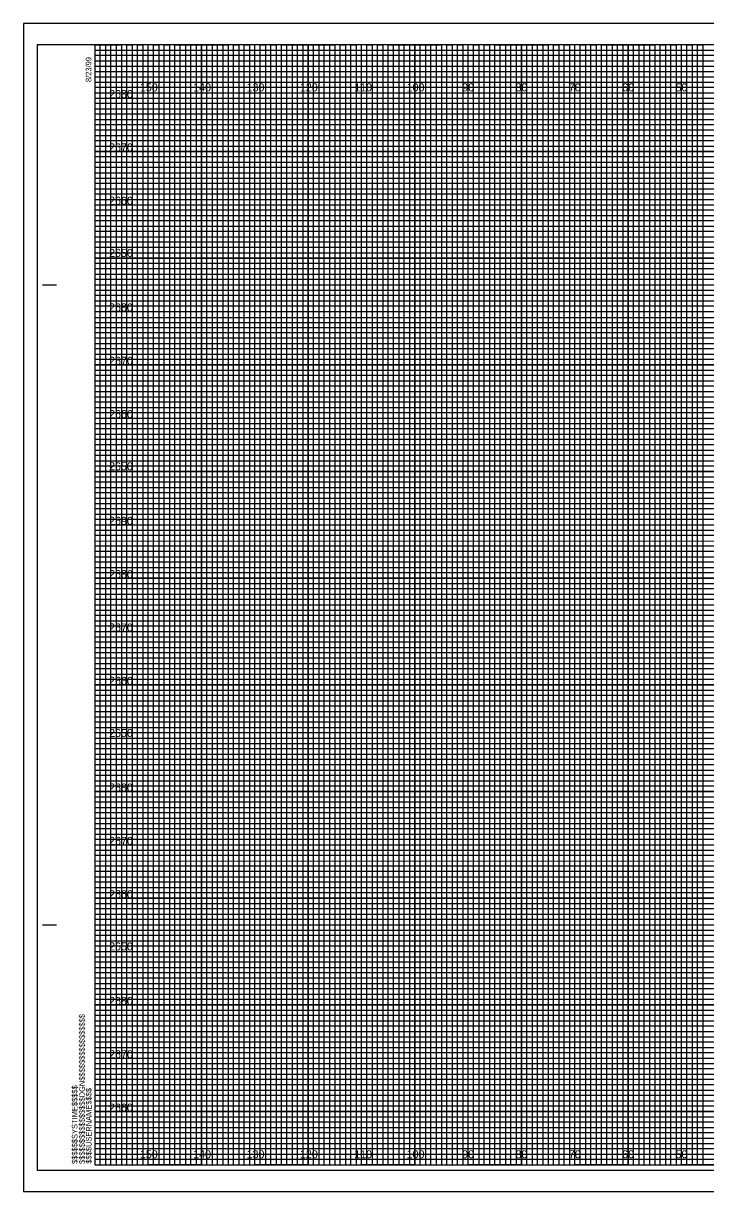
# Model space of a CAD drawing. Extents: x -13 to 323, y -5 to 214.
# Drawn here: x -13.4 to 114.5, y -5 to 214 of the extents above; entities that cross this region are included whole.
import ezdxf

# ---------------------------------------------------------------- set-up
doc = ezdxf.new("R2010")
doc.units = 0
for name, color, linetype in [('Prop XS Elevation Labels', 7, 'Continuous'), ('Prop XS Offset Labels', 7, 'Continuous'), ('Sheet Cross Section CELL', 7, 'Continuous'), ('Sheet Cross Section Grid Major CELL', 7, 'Continuous'), ('Sheet Cross Section Grid Middle CELL', 7, 'Continuous'), ('Sheet Cross Section Grid Minor 1 CELL', 7, 'Continuous'), ('Sheet Cross Section Grid Minor 2 CELL', 7, 'Continuous'), ('Sheet Cutting Line CELL', 7, 'Continuous'), ('Sheet DOT Grid CELL', 7, 'Continuous'), ('Sheet Plot Border Inside CELL', 7, 'Continuous'), ('Sheet Plot Border Outside CELL', 7, 'Continuous')]:
    doc.layers.add(name, color=color, linetype=linetype)

msp = doc.modelspace()

# ---------------------------------------------------------------- linework, layer by layer
at = {"layer": 'Sheet Cross Section CELL'}
for p, q in [((-9.8, 165), (-7.3, 165)), ((-9.7, 165), (-7.2, 165)), ((-9.8, 45), (-7.3, 45)), ((-9.7, 45), (-7.2, 45)), ((0, 0), (0, 0)), ((0, 0), (0, 0)), ((0, 0), (0, 0)), ((0, 0), (0, 0)), ((0, 0), (0, 0)), ((0, 0), (0, 0)), ((0, 0), (0, 0))]:
    msp.add_line(p, q, dxfattribs=at)
msp.add_lwpolyline([(320, 210), (0, 210), (0, 0), (320, 0)], close=True, dxfattribs=at)
at = {"layer": 'Sheet Cross Section Grid Major CELL'}
for p, q in [((10, 210), (0, 210)), ((10, 0), (10, 210)), ((30, 210), (20, 210)), ((20, 210), (20, 0)), ((30, 0), (30, 210)), ((50, 210), (40, 210)), ((40, 210), (40, 0)), ((50, 0), (50, 210)), ((70, 210), (60, 210)), ((60, 210), (60, 0)), ((70, 0), (70, 210)), ((90, 210), (80, 210)), ((80, 210), (80, 0)), ((90, 0), (90, 210)), ((110, 210), (100, 210)), ((100, 210), (100, 0)), ((110, 0), (110, 210)), ((20, 0), (10, 0)), ((40, 0), (30, 0)), ((60, 0), (50, 0)), ((80, 0), (70, 0)), ((100, 0), (90, 0)), ((120, 0), (110, 0))]:
    msp.add_line(p, q, dxfattribs=at)
for points in [[(0, 200), (320, 200), (320, 190), (0, 190)], [(0, 180), (320, 180), (320, 170), (0, 170)], [(0, 160), (320, 160), (320, 150), (0, 150)], [(0, 140), (320, 140), (320, 130), (0, 130)], [(0, 120), (320, 120), (320, 110), (0, 110)], [(0, 100), (320, 100), (320, 90), (0, 90)], [(0, 80), (320, 80), (320, 70), (0, 70)], [(0, 60), (320, 60), (320, 50), (0, 50)], [(0, 40), (320, 40), (320, 30), (0, 30)], [(0, 20), (320, 20), (320, 10), (0, 10)]]:
    msp.add_lwpolyline(points, dxfattribs=at)
at = {"layer": 'Sheet Cross Section Grid Middle CELL'}
for points in [[(0, 210), (5, 210), (5, 0), (15, 0), (15, 210), (25, 210), (25, 0), (35, 0), (35, 210), (45, 210), (45, 0), (55, 0), (55, 210), (65, 210), (65, 0), (75, 0), (75, 210), (85, 210), (85, 0), (95, 0), (95, 210), (105, 210), (105, 0), (115, 0)], [(0, 205), (275, 205)], [(0, 185), (320, 185), (320, 195), (0, 195)], [(0, 165), (320, 165), (320, 175), (0, 175)], [(0, 145), (320, 145), (320, 155), (0, 155)], [(0, 125), (320, 125), (320, 135), (0, 135)], [(0, 105), (320, 105), (320, 115), (0, 115)], [(0, 85), (320, 85), (320, 95), (0, 95)], [(0, 65), (320, 65), (320, 75), (0, 75)], [(0, 45), (320, 45), (320, 55), (0, 55)], [(0, 25), (320, 25), (320, 35), (0, 35)], [(0, 5), (320, 5), (320, 15), (0, 15)]]:
    msp.add_lwpolyline(points, dxfattribs=at)
at = {"layer": 'Sheet Cross Section Grid Minor 1 CELL'}
for p, q in [((0, 209), (260, 209)), ((260, 207.98), (0, 207.98)), ((0, 207.98), (0, 207)), ((0, 207), (260, 207)), ((260, 205.89), (0, 205.89)), ((0, 205.89), (0, 204)), ((0, 204), (320, 204))]:
    msp.add_line(p, q, dxfattribs=at)
for points in [[(0, 203), (270, 203), (320, 203), (320, 202), (0, 202)], [(0, 201), (320, 201), (320, 199), (0, 199)], [(0, 198), (320, 198), (320, 197), (0, 196.98)], [(0, 196), (320, 196), (320, 194), (0, 194)], [(0, 193), (320, 193), (320, 192), (0, 192)], [(0, 191), (320, 191), (320, 189), (0, 189)], [(0, 188), (320, 188), (320, 187), (0, 187)], [(0, 186), (320, 186), (320, 184), (0, 184)], [(0, 183), (320, 183), (320, 182), (0, 182)], [(0, 181), (320, 181), (320, 179), (0, 179)], [(0, 178), (320, 178), (320, 177), (0, 177)], [(0, 176), (320, 176), (320, 173.95), (320, 173), (320, 172), (0, 172)], [(0, 174), (320, 174), (320, 173), (0, 173)], [(0, 171), (320, 171), (320, 169), (0, 169.03)], [(0, 169.03), (320, 169), (320, 168), (0, 168)], [(0, 167), (320, 167), (320, 166), (0, 166)], [(0, 164), (320, 164), (320, 163), (0, 163)], [(0, 162), (320, 162), (320, 161), (0, 161)], [(-0.07, 158.89), (320, 158.89), (320, 157.88), (-0.07, 157.88)], [(0, 157), (320, 157), (320, 156), (0, 156)], [(0, 154), (320, 154), (320, 153), (0, 153)], [(0, 152), (320, 152), (320, 151), (0, 151)], [(0, 149), (320, 149), (320, 148), (0, 148)], [(0, 147), (320, 147), (320, 146), (0, 146)], [(0, 144), (320, 144), (320, 143), (0, 143)], [(0, 142), (320, 142), (320, 141), (0, 141)], [(0, 139), (320, 139), (319.99, 137.98), (0, 138)], [(0, 137), (320, 137), (320, 136), (0, 136)], [(0, 134), (320, 134), (320, 133), (0, 133)], [(0, 132), (320, 132), (320, 131), (0, 131)], [(0, 129), (320, 129), (320, 128), (0, 128)], [(0, 127), (320, 127), (320, 126), (0, 126)], [(0, 124), (320, 124), (320, 123), (0, 123)], [(0, 122), (320, 122), (320, 121), (0, 121)], [(0, 119), (320, 119), (320, 118), (0, 118)], [(0, 116.99), (320.07, 116.91), (320, 116), (0, 116)], [(0, 114), (320, 114), (320, 113), (0, 113)], [(0, 112), (320, 112), (320, 111), (0, 111)], [(0, 109), (320, 109), (320, 108), (0, 108)], [(0, 107), (320, 107), (320, 106), (0, 106)], [(0, 104), (320, 104), (320, 103), (0, 103)], [(0, 102), (320, 102), (320, 101), (0, 101)], [(0, 99), (320, 99), (320, 98), (0, 98)], [(0, 97), (320, 97), (320, 96), (0, 96)], [(0, 94), (320, 94), (320, 93), (0, 93)], [(0, 92), (320, 92), (320, 91), (0, 91)], [(0, 89), (320, 89), (320, 88), (0, 88)], [(0, 87), (320, 87), (320, 86), (0, 86)], [(0, 84), (320, 84), (320, 83), (0, 83)], [(0, 82), (320, 82), (320, 81), (0, 81)], [(0, 79), (320, 79), (319.99, 77.98), (0, 78)], [(0, 77), (320, 77), (320, 76), (0, 76)], [(0, 74), (320, 74), (320, 73), (0, 73)], [(0, 72), (320, 72), (320, 71), (0, 71)], [(0, 69), (320, 69), (320, 68), (0, 68)], [(0, 67), (320, 67), (320, 66), (0, 66)], [(0, 64), (320, 64), (320, 63), (0, 63)], [(0, 62), (320, 62), (320, 61), (0, 61)], [(0, 59), (320, 59), (320, 58), (0, 58)], [(0, 56.99), (320.07, 56.91), (320, 56), (0, 56)], [(0, 54), (320, 54), (320, 53), (0, 53)], [(0, 52), (320, 52), (320, 51), (0, 51)], [(0, 49), (320, 49), (320, 48), (0, 48)], [(0, 47), (320, 47), (320, 46), (0, 46)], [(0, 44), (320, 44), (320, 43), (0, 43)], [(0, 42), (320, 42), (320, 41), (0, 41)], [(0, 39), (320, 39), (320, 38), (0, 38)], [(0, 37), (320, 37), (320, 36), (0, 36)], [(0, 34), (320, 34), (320, 33), (0, 33)], [(0, 32), (320, 32), (320, 31), (0, 31)], [(0, 29), (320, 29), (320, 28), (0, 28)], [(0, 27), (320, 27), (320, 26), (0, 26)], [(0, 24), (320, 24), (320, 23), (0, 23)], [(0, 22), (320, 22), (320, 21), (0, 21)], [(0, 19), (320, 19), (320, 18), (0, 18)], [(0, 17), (320, 17), (320, 16), (0, 16)], [(0, 14), (320, 14), (320, 13), (0, 13)], [(0, 12), (320, 12), (320, 11), (0, 11)], [(0, 9), (320, 9), (320, 8), (0, 8)], [(0, 7), (320, 7), (320, 6), (0, 6)], [(0, 4), (320, 4), (320, 3), (0, 3)], [(0, 2), (320, 2), (320, 1), (0, 1)]]:
    msp.add_lwpolyline(points, dxfattribs=at)
at = {"layer": 'Sheet Cross Section Grid Minor 2 CELL'}
for points in [[(0, 0), (1, 0), (1, 210), (2, 210), (2, 0)], [(2, 0), (3, 0), (3, 210), (4, 210), (4, 0)], [(5, 0), (6, 0), (6, 210), (7, 210), (7, 0)], [(7, 0), (8, 0), (8, 210), (9, 210), (9, 0)], [(10, 0), (11, 0), (11, 210), (12, 210), (12, 0)], [(12, 0), (13, 0), (13, 210), (14, 210), (14, 0)], [(15, 0), (16, 0), (16, 210), (17, 210), (17, 0)], [(17, 0), (18, 0), (18, 210), (19, 210), (19, 0)], [(20, 0), (21, 0), (21, 210), (22, 210), (22, 0)], [(22, 0), (23, 0), (23, 210), (24, 210), (24, 0)], [(25, 0), (26, 0), (26, 210), (27, 210), (27, 0)], [(27, 0), (28, 0), (28, 210), (29, 210), (29, 0)], [(30, 0), (31, 0), (31, 210), (32, 210), (32, 0)], [(32, 0), (33, 0), (33, 210), (34, 210), (34, 0)], [(35, 0), (36, 0), (36, 210), (37, 210), (37, 0)], [(37, 0), (38, 0), (38, 210), (39, 210), (39, 0)], [(40, 0), (41, 0), (41, 210), (42, 210), (42, 0)], [(42, 0), (43, 0), (43, 210), (44, 210), (44, 0)], [(45, 0), (46, 0), (46, 210), (47, 210), (47, 0)], [(47, 0), (48, 0), (48, 210), (49, 210), (49, 0)], [(50, 0), (51, 0), (51, 210), (52, 210), (52, 0)], [(52, 0), (53, 0), (53, 210), (54, 210), (54, 0)], [(55, 0), (56, 0), (56, 210), (57, 210), (57, 0)], [(57, 0), (58, 0), (58, 210), (59, 210), (59, 0)], [(60, 0), (61, 0), (61, 210), (62, 210), (62, 0)], [(62, 0), (63, 0), (63, 210), (64, 210), (64, 0)], [(65, 0), (66, 0), (66, 210), (67, 210), (67, 0)], [(67, 0), (68, 0), (68, 210), (69, 210), (69, 0)], [(70, 0), (71, 0), (71, 210), (72, 210), (72, 0)], [(72, 0), (73, 0), (73, 210), (74, 210), (74, 0)], [(75, 0), (76, 0), (76, 210), (77, 210), (77, 0)], [(77, 0), (78, 0), (78, 210), (79, 210), (79, 0)], [(80, 0), (81, 0), (81, 210), (82, 210), (82, 0)], [(82, 0), (83, 0), (83, 210), (84, 210), (84, 0)], [(85, 0), (86, 0), (86, 210), (87, 210), (87, 0)], [(87, 0), (88, 0), (88, 210), (89, 210), (89, 0)], [(90, 0), (91, 0), (91, 210), (92, 210), (92, 0)], [(92, 0), (93, 0), (93, 210), (94, 210), (94, 0)], [(95, 0), (96, 0), (96, 210), (97, 210), (97, 0)], [(97, 0), (98, 0), (98, 210), (99, 210), (99, 0)], [(100, 0), (101, 0), (101, 210), (102, 210), (102, 0)], [(102, 0), (103, 0), (103, 210), (104, 210), (104, 0)], [(105, 0), (106, 0), (106, 210), (107, 210), (107, 0)], [(107, 0), (108, 0), (108, 210), (109, 210), (109, 0)], [(110, 0), (111, 0), (111, 210), (112, 210), (112, 0)], [(112, 0), (113, 0), (113, 210), (114, 210), (114, 0)]]:
    msp.add_lwpolyline(points, dxfattribs=at)
at = {"layer": 'Sheet Cutting Line CELL'}
for p, q in [((323.3, 214), (-13.4, 214)), ((-13.4, 214), (-13.4, -5)), ((-13.4, -5), (323.3, -5))]:
    msp.add_line(p, q, dxfattribs=at)
at = {"layer": 'Sheet DOT Grid CELL'}
for p, q in [((10, 0), (10, 210)), ((20, 0), (20, 210)), ((30, 0), (30, 210)), ((40, 0), (40, 210)), ((50, 0), (50, 210)), ((60, 0), (60, 210)), ((70, 0), (70, 210)), ((80, 0), (80, 210)), ((90, 0), (90, 210)), ((100, 0), (100, 210)), ((110, 0), (110, 210)), ((0, 200), (320, 200)), ((0, 190), (320, 190)), ((0, 180), (320, 180)), ((0, 170), (320, 170)), ((0, 160), (320, 160)), ((0, 150), (320, 150)), ((0, 140), (320, 140)), ((0, 130), (320, 130)), ((0, 120), (320, 120)), ((0, 110), (320, 110)), ((0, 100), (320, 100)), ((0, 90), (320, 90)), ((0, 80), (320, 80)), ((0, 70), (320, 70)), ((0, 60), (320, 60)), ((0, 50), (320, 50)), ((0, 40), (320, 40)), ((0, 30), (320, 30)), ((0, 20), (320, 20)), ((0, 10), (320, 10))]:
    msp.add_line(p, q, dxfattribs=at)
at = {"layer": 'Sheet Plot Border Inside CELL'}
msp.add_lwpolyline([(-10.8, -1), (322.4, -1), (322.4, 210), (-10.8, 210)], close=True, dxfattribs=at)
at = {"layer": 'Sheet Plot Border Outside CELL'}
msp.add_lwpolyline([(-13.4, -5), (323.3, -5), (323.3, 214), (-13.4, 214)], close=True, dxfattribs=at)

# ---------------------------------------------------------------- texts
at = {"layer": 'Prop XS Elevation Labels'}
for s, p in [('2680', (2.67, 200)), ('2670', (2.67, 190)), ('2660', (2.67, 180)), ('2650', (2.67, 170.22)), ('2680', (2.67, 160)), ('2670', (2.67, 150)), ('2660', (2.67, 140)), ('2650', (2.67, 130.22)), ('2690', (2.67, 120)), ('2680', (2.67, 110)), ('2670', (2.67, 100)), ('2660', (2.67, 90)), ('2650', (2.67, 80.22)), ('2680', (2.67, 70)), ('2670', (2.67, 60)), ('2660', (2.67, 50)), ('2650', (2.67, 40.22)), ('2680', (2.67, 30)), ('2670', (2.67, 20)), ('2660', (2.67, 10))]:
    msp.add_text(s, height=1.5, dxfattribs=at).set_placement(p)
at = {"layer": 'Prop XS Offset Labels'}
for s, p in [('150', (8.44, 201.25)), ('140', (18.44, 201.25)), ('130', (28.44, 201.25)), ('120', (38.44, 201.25)), ('110', (48.62, 201.25)), ('100', (58.44, 201.25)), ('90', (68.86, 201.25)), ('80', (78.86, 201.25)), ('70', (88.86, 201.25)), ('60', (98.86, 201.25)), ('50', (108.86, 201.25)), ('150', (8.44, 1.25)), ('140', (18.44, 1.25)), ('130', (28.44, 1.25)), ('120', (38.44, 1.25)), ('110', (48.62, 1.25)), ('100', (58.44, 1.25)), ('90', (68.86, 1.25)), ('80', (78.86, 1.25)), ('70', (88.86, 1.25)), ('60', (98.86, 1.25)), ('50', (108.86, 1.25))]:
    msp.add_text(s, height=1.5, dxfattribs=at).set_placement(p)
at = {"layer": 'Sheet Cross Section CELL'}
for s, p in [('8/23/99', (-0.65, 203)), ('$$$$$$$$$$$$$$$$DGN$$$$$$$$$$$$$$$$', (-1.88, 0.18)), ('$$$$$$SYSTIME$$$$$', (-3.26, 0.18)), ('$$$$USERNAME$$$$', (-0.62, 0.23))]:
    msp.add_text(s, height=1.05, rotation=90, dxfattribs=at).set_placement(p)

doc.saveas('drawing.dxf')
